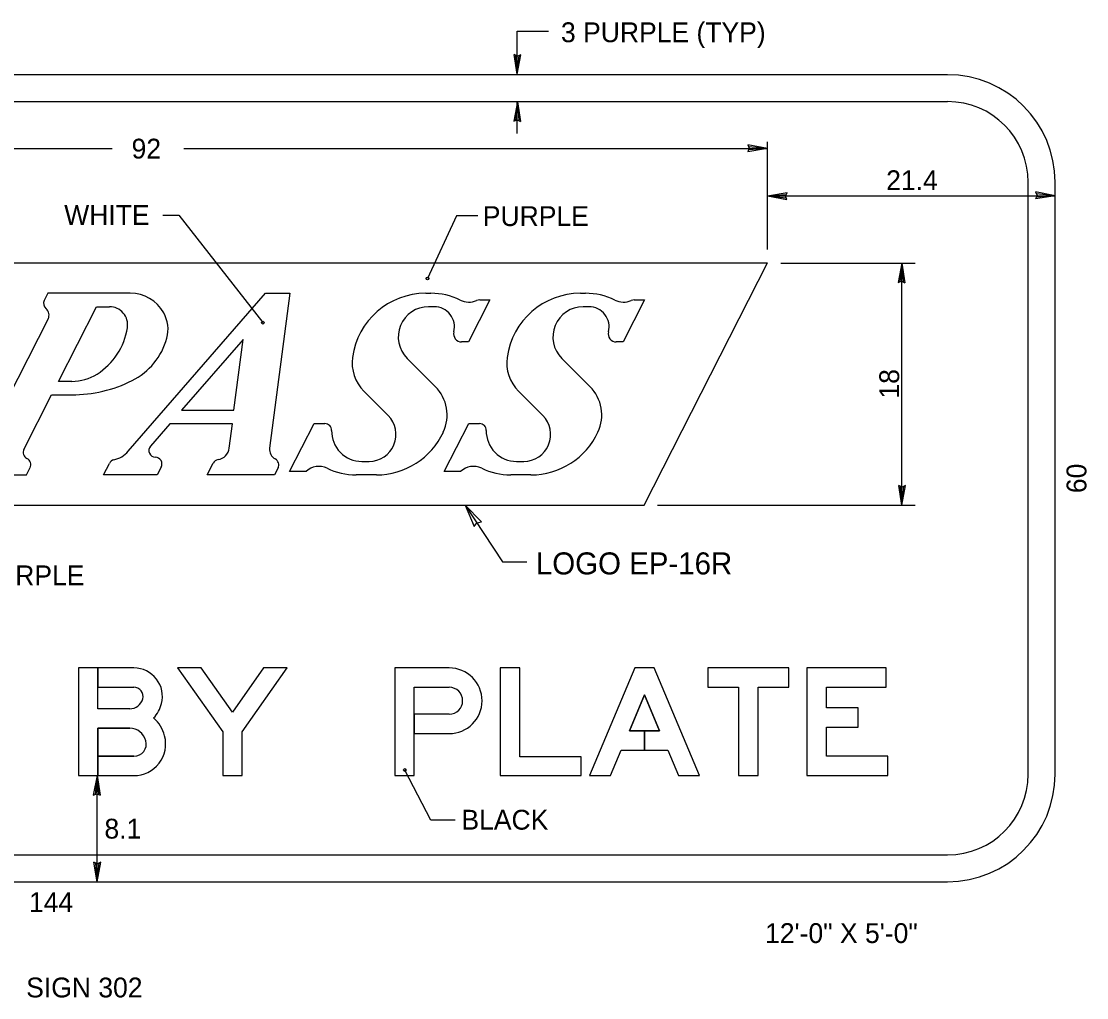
# Model space of a CAD drawing. Extents: x 319706 to 320449, y 1621775 to 1622117.
# Drawn here: x 319941.2 to 320016.4, y 1622047.8 to 1622116.7 of the extents above; entities that cross this region are included whole.
import ezdxf

# ---------------------------------------------------------------- set-up
doc = ezdxf.new("R2010")
doc.units = 0
for name, color, linetype in [('1', 7, 'Continuous'), ('52', 7, 'Continuous'), ('GSBWFill', 7, 'Continuous'), ('SignPanel', 7, 'Continuous')]:
    doc.layers.add(name, color=color, linetype=linetype)

msp = doc.modelspace()

# ---------------------------------------------------------------- linework, layer by layer
at = {"layer": '1'}
for p, q in [((319976.192, 1622116.021), (319978.396, 1622116.007)), ((319976.192, 1622112.926), (319976.192, 1622116.021)), ((319976.192, 1622108.782), (319976.192, 1622111.041)), ((319993.862, 1622100.591), (319993.862, 1622108.191)), ((319906.462, 1622107.716), (319947.578, 1622107.716)), ((319952.634, 1622107.716), (319993.862, 1622107.716)), ((319993.862, 1622104.391), (320014.192, 1622104.391)), ((319951.159, 1622103.026), (319952.29, 1622103.026)), ((319952.29, 1622103.026), (319958.216, 1622095.427)), ((319971.899, 1622102.972), (319969.851, 1622098.552)), ((319973.407, 1622102.972), (319971.899, 1622102.972)), ((319994.812, 1622099.639), (320004.312, 1622099.639)), ((320003.362, 1622082.539), (320003.362, 1622099.639)), ((319972.523, 1622082.541), (319975.141, 1622078.543)), ((319986.099, 1622082.539), (320004.312, 1622082.539)), ((319975.141, 1622078.543), (319976.861, 1622078.543)), ((319970.079, 1622060.29), (319968.252, 1622063.833)), ((319946.507, 1622055.939), (319946.507, 1622063.439)), ((319971.815, 1622060.29), (319970.079, 1622060.29))]:
    msp.add_line(p, q, dxfattribs=at)
for centre in [(319969.851, 1622098.552), (319958.216, 1622095.426), (319968.252, 1622063.833)]:
    msp.add_circle(centre, 0.095, dxfattribs=at)
at = {"layer": '52'}
for p, q in [((319976.185, 1622112.964), (319975.965, 1622114.353)), ((319976.207, 1622114.243), (319975.965, 1622114.353)), ((319976.185, 1622112.964), (319976.092, 1622114.294)), ((319976.185, 1622112.964), (319976.453, 1622114.345)), ((319976.185, 1622112.964), (319976.324, 1622114.291)), ((319976.453, 1622114.345), (319976.207, 1622114.243)), ((319976.211, 1622111.028), (319975.943, 1622109.648)), ((319976.211, 1622111.028), (319976.072, 1622109.701)), ((319976.211, 1622111.028), (319976.431, 1622109.639)), ((319976.211, 1622111.028), (319976.304, 1622109.698)), ((319975.943, 1622109.648), (319976.189, 1622109.749)), ((319976.189, 1622109.749), (319976.431, 1622109.639)), ((319993.862, 1622107.716), (319992.481, 1622107.984)), ((319992.481, 1622107.984), (319992.583, 1622107.738)), ((319992.583, 1622107.738), (319992.473, 1622107.496)), ((319993.862, 1622107.716), (319992.473, 1622107.496)), ((319993.862, 1622107.716), (319992.532, 1622107.623)), ((319993.862, 1622107.716), (319992.534, 1622107.855)), ((319993.862, 1622104.391), (319995.251, 1622104.612)), ((319993.862, 1622104.391), (319995.192, 1622104.484)), ((319993.862, 1622104.391), (319995.242, 1622104.123)), ((319993.862, 1622104.391), (319995.189, 1622104.253)), ((319995.14, 1622104.37), (319995.251, 1622104.612)), ((319995.242, 1622104.123), (319995.14, 1622104.37)), ((320012.913, 1622104.413), (320012.803, 1622104.171)), ((320014.192, 1622104.391), (320012.803, 1622104.171)), ((320014.192, 1622104.391), (320012.811, 1622104.659)), ((320012.811, 1622104.659), (320012.913, 1622104.413)), ((320014.192, 1622104.391), (320012.862, 1622104.298)), ((320014.192, 1622104.391), (320012.864, 1622104.53)), ((320003.362, 1622099.639), (320003.094, 1622098.259)), ((320003.362, 1622099.639), (320003.223, 1622098.312)), ((320003.362, 1622099.639), (320003.582, 1622098.25)), ((320003.362, 1622099.639), (320003.455, 1622098.309)), ((320003.094, 1622098.259), (320003.34, 1622098.361)), ((320003.34, 1622098.361), (320003.582, 1622098.25)), ((320003.362, 1622082.539), (320003.141, 1622083.928)), ((320003.383, 1622083.818), (320003.141, 1622083.928)), ((320003.362, 1622082.539), (320003.269, 1622083.869)), ((320003.362, 1622082.539), (320003.63, 1622083.92)), ((320003.362, 1622082.539), (320003.5, 1622083.867)), ((320003.63, 1622083.92), (320003.383, 1622083.818)), ((319972.523, 1622082.541), (319973.146, 1622081.022)), ((319973.657, 1622081.357), (319972.523, 1622082.541)), ((319973.146, 1622081.022), (319973.339, 1622081.295)), ((319973.339, 1622081.295), (319973.657, 1622081.357)), ((319946.507, 1622063.439), (319946.239, 1622062.059)), ((319946.507, 1622063.439), (319946.368, 1622062.112)), ((319946.507, 1622063.439), (319946.727, 1622062.05)), ((319946.507, 1622063.439), (319946.6, 1622062.109)), ((319946.239, 1622062.059), (319946.485, 1622062.16)), ((319946.485, 1622062.16), (319946.727, 1622062.05)), ((319946.507, 1622055.939), (319946.287, 1622057.328)), ((319946.529, 1622057.218), (319946.287, 1622057.328)), ((319946.507, 1622055.939), (319946.414, 1622057.269)), ((319946.507, 1622055.939), (319946.775, 1622057.32)), ((319946.507, 1622055.939), (319946.646, 1622057.267)), ((319946.775, 1622057.32), (319946.529, 1622057.218))]:
    msp.add_line(p, q, dxfattribs=at)
at = {"layer": 'GSBWFill'}
for p, q in [((319968.912, 1622069.672), (319971.383, 1622069.672)), ((319968.912, 1622069.672), (319971.383, 1622069.672)), ((319968.912, 1622069.672), (319971.383, 1622069.672)), ((319968.912, 1622066.403), (319971.383, 1622066.403)), ((319945.195, 1622063.439), (319949.11, 1622063.439))]:
    msp.add_line(p, q, dxfattribs=at)
for points in [[(319949.11, 1622071.041), (319945.195, 1622071.041), (319945.195, 1622063.439)], [(319948.815, 1622068.152), (319946.563, 1622068.152), (319946.563, 1622071.041), (319945.195, 1622071.041), (319945.195, 1622063.439), (319946.563, 1622063.439)], [(319948.815, 1622068.152), (319946.563, 1622068.152), (319946.563, 1622071.041), (319945.195, 1622071.041), (319945.195, 1622063.439), (319946.563, 1622063.439)], [(319949.11, 1622071.041), (319946.563, 1622071.041), (319946.563, 1622069.672), (319949.11, 1622069.672)], [(319949.11, 1622071.041), (319946.563, 1622071.041), (319946.563, 1622069.672), (319949.11, 1622069.672)], [(319971.383, 1622071.041), (319967.544, 1622071.041), (319967.544, 1622063.439), (319968.912, 1622063.439), (319968.912, 1622066.403)], [(319971.383, 1622071.041), (319967.544, 1622071.041), (319967.544, 1622063.439), (319968.912, 1622063.439), (319968.912, 1622069.672)], [(319971.383, 1622071.041), (319967.544, 1622071.041), (319967.544, 1622063.439), (319968.912, 1622063.439), (319968.912, 1622069.672)], [(319948.815, 1622068.152), (319946.563, 1622068.152), (319946.563, 1622069.672), (319949.11, 1622069.672)], [(319971.383, 1622067.772), (319968.912, 1622067.772), (319968.912, 1622069.672)], [(319971.383, 1622067.772), (319968.913, 1622067.772), (319968.913, 1622066.403), (319971.383, 1622066.403)], [(319971.383, 1622067.772), (319968.913, 1622067.772), (319968.913, 1622066.403), (319971.383, 1622066.403)], [(319948.815, 1622066.784), (319946.563, 1622066.784), (319946.563, 1622064.807), (319949.11, 1622064.807)], [(319946.563, 1622063.439), (319946.563, 1622066.784), (319948.815, 1622066.784)], [(319946.563, 1622063.439), (319946.563, 1622066.784), (319948.815, 1622066.784)], [(319949.11, 1622064.807), (319946.563, 1622064.807), (319946.563, 1622063.439), (319949.11, 1622063.439)], [(319949.11, 1622064.807), (319946.563, 1622064.807), (319946.563, 1622063.439), (319949.11, 1622063.439)]]:
    msp.add_lwpolyline(points, dxfattribs=at)
for points in [[(319956.749, 1622066.518), (319959.942, 1622071.041), (319958.267, 1622071.041), (319956.065, 1622067.921), (319953.863, 1622071.041), (319952.188, 1622071.041), (319955.381, 1622066.518), (319955.381, 1622063.439), (319956.749, 1622063.439)], [(319956.749, 1622066.518), (319959.942, 1622071.041), (319958.267, 1622071.041), (319956.065, 1622067.921), (319953.863, 1622071.041), (319952.188, 1622071.041), (319955.381, 1622066.518), (319955.381, 1622063.439), (319956.749, 1622063.439)], [(319956.749, 1622066.518), (319959.942, 1622071.041), (319958.267, 1622071.041), (319956.065, 1622067.921), (319953.863, 1622071.041), (319952.188, 1622071.041), (319955.381, 1622066.518), (319955.381, 1622063.439), (319956.749, 1622063.439)], [(319980.695, 1622063.439), (319980.695, 1622064.769), (319976.362, 1622064.769), (319976.362, 1622071.041), (319974.994, 1622071.041), (319974.994, 1622063.439)], [(319980.695, 1622063.439), (319980.695, 1622064.769), (319976.362, 1622064.769), (319976.362, 1622071.041), (319974.994, 1622071.041), (319974.994, 1622063.439)], [(319980.695, 1622063.439), (319980.695, 1622064.769), (319976.362, 1622064.769), (319976.362, 1622071.041), (319974.994, 1622071.041), (319974.994, 1622063.439)], [(319983.537, 1622065.225), (319986.822, 1622065.225), (319987.573, 1622063.439), (319989.057, 1622063.439), (319985.864, 1622071.041), (319984.496, 1622071.041), (319981.303, 1622063.439), (319982.787, 1622063.439)], [(319986.248, 1622066.594), (319985.18, 1622066.594), (319985.18, 1622065.225), (319986.822, 1622065.225), (319987.573, 1622063.439), (319989.057, 1622063.439), (319985.864, 1622071.041), (319984.496, 1622071.041), (319981.303, 1622063.439), (319982.787, 1622063.439), (319983.537, 1622065.225), (319985.18, 1622065.225), (319985.18, 1622066.594), (319984.112, 1622066.594), (319985.18, 1622069.136)], [(319986.248, 1622066.594), (319985.18, 1622066.594), (319985.18, 1622065.225), (319986.822, 1622065.225), (319987.573, 1622063.439), (319989.057, 1622063.439), (319985.864, 1622071.041), (319984.496, 1622071.041), (319981.303, 1622063.439), (319982.787, 1622063.439), (319983.537, 1622065.225), (319985.18, 1622065.225), (319985.18, 1622066.594), (319984.112, 1622066.594), (319985.18, 1622069.136)], [(319989.665, 1622069.672), (319991.831, 1622069.672), (319991.831, 1622063.439), (319993.2, 1622063.439), (319993.2, 1622069.672), (319995.366, 1622069.672), (319995.366, 1622071.041), (319989.665, 1622071.041)], [(319989.665, 1622069.672), (319991.831, 1622069.672), (319991.831, 1622063.439), (319993.2, 1622063.439), (319993.2, 1622069.672), (319995.366, 1622069.672), (319995.366, 1622071.041), (319989.665, 1622071.041)], [(319989.665, 1622069.672), (319991.831, 1622069.672), (319991.831, 1622063.439), (319993.2, 1622063.439), (319993.2, 1622069.672), (319995.366, 1622069.672), (319995.366, 1622071.041), (319989.665, 1622071.041)], [(320002.36, 1622064.807), (319998.027, 1622064.807), (319998.027, 1622066.852), (320000.269, 1622066.852), (320000.269, 1622068.22), (319998.027, 1622068.22), (319998.027, 1622069.672), (320002.246, 1622069.672), (320002.246, 1622071.041), (319996.659, 1622071.041), (319996.659, 1622063.439), (320002.36, 1622063.439)], [(320002.36, 1622064.807), (319998.027, 1622064.807), (319998.027, 1622066.852), (320000.269, 1622066.852), (320000.269, 1622068.22), (319998.027, 1622068.22), (319998.027, 1622069.672), (320002.246, 1622069.672), (320002.246, 1622071.041), (319996.659, 1622071.041), (319996.659, 1622063.439), (320002.36, 1622063.439)], [(320002.36, 1622064.807), (319998.027, 1622064.807), (319998.027, 1622066.852), (320000.269, 1622066.852), (320000.269, 1622068.22), (319998.027, 1622068.22), (319998.027, 1622069.672), (320002.246, 1622069.672), (320002.246, 1622071.041), (319996.659, 1622071.041), (319996.659, 1622063.439), (320002.36, 1622063.439)], [(319986.248, 1622066.594), (319985.18, 1622069.136), (319984.112, 1622066.594)]]:
    msp.add_lwpolyline(points, close=True, dxfattribs=at)
for centre, radius, start, end in [((319949.11, 1622069.026), 2.014, 345.52249, 90), ((319949.11, 1622069.026), 2.014, 345.52249, 90), ((319949.11, 1622069.026), 2.014, 345.52249, 90), ((319949.11, 1622069.026), 0.646, 345.52249, 90), ((319949.11, 1622069.026), 0.646, 345.52249, 90), ((319949.11, 1622069.026), 0.646, 345.52249, 90), ((319948.815, 1622069.102), 0.95, 270, 345.52249), ((319948.815, 1622069.102), 0.95, 270, 345.52249), ((319948.815, 1622069.102), 0.95, 270, 345.52249), ((319948.815, 1622069.102), 2.319, 316.7114, 345.52249), ((319948.815, 1622069.102), 2.319, 316.7114, 345.52249), ((319948.815, 1622069.102), 2.319, 316.7114, 345.52249), ((319948.815, 1622065.605), 2.547, 14.47751, 48.4921), ((319948.815, 1622065.605), 2.547, 14.47751, 48.4921), ((319948.815, 1622065.605), 2.547, 14.47751, 48.4921), ((319948.815, 1622065.605), 1.178, 14.47751, 90), ((319948.815, 1622065.605), 1.178, 14.47751, 90), ((319948.815, 1622065.605), 1.178, 14.47751, 90), ((319949.11, 1622065.681), 2.243, 270, 14.47751), ((319949.11, 1622065.681), 2.243, 270, 14.47751), ((319949.11, 1622065.681), 2.243, 270, 14.47751), ((319949.11, 1622065.681), 0.874, 270, 14.47751), ((319949.11, 1622065.681), 0.874, 270, 14.47751), ((319949.11, 1622065.681), 0.874, 270, 14.47751)]:
    msp.add_arc(centre, radius, start, end, dxfattribs=at)
for major_axis in [(0, 2.319), (0, 2.319), (0, 2.319), (0, 0.95), (0, 0.95), (0, 0.95)]:
    msp.add_ellipse((319971.383, 1622068.722), major_axis=major_axis, ratio=0.999994, start_param=3.141593, end_param=6.283185, dxfattribs=at)
at = {"layer": 'SignPanel'}
for p, q in [((319884.992, 1622112.941), (320006.593, 1622112.941)), ((319884.992, 1622111.041), (320006.593, 1622111.041)), ((320012.293, 1622063.541), (320012.293, 1622105.341)), ((320014.193, 1622063.541), (320014.193, 1622105.341)), ((319939.669, 1622099.641), (319993.863, 1622099.641)), ((319985.149, 1622082.541), (319993.863, 1622099.641)), ((319943.037, 1622097.503), (319942.778, 1622096.996)), ((319948.855, 1622097.503), (319943.037, 1622097.503)), ((319948.709, 1622086.346), (319958.41, 1622097.503)), ((319958.41, 1622097.503), (319960.12, 1622097.503)), ((319960.12, 1622097.503), (319958.698, 1622086.571)), ((319969.729, 1622097.503), (319970.089, 1622097.503)), ((319980.655, 1622097.503), (319981.015, 1622097.503)), ((319974.248, 1622097.027), (319972.738, 1622094.065)), ((319973.536, 1622097.027), (319974.248, 1622097.027)), ((319985.174, 1622097.027), (319983.664, 1622094.065)), ((319984.46, 1622097.027), (319985.174, 1622097.027)), ((319943.782, 1622091.281), (319946.47, 1622096.553)), ((319946.47, 1622096.553), (319947.386, 1622096.553)), ((319970.33, 1622096.553), (319969.924, 1622096.553)), ((319981.256, 1622096.553), (319980.848, 1622096.553)), ((319943.053, 1622095.707), (319938.349, 1622086.476)), ((319956.819, 1622094.226), (319952.482, 1622089.237)), ((319956.17, 1622089.237), (319956.819, 1622094.226)), ((319972.738, 1622094.065), (319972.264, 1622094.065)), ((319983.664, 1622094.065), (319983.188, 1622094.065)), ((319968.411, 1622092.904), (319970.402, 1622090.913)), ((319979.337, 1622092.904), (319981.328, 1622090.913)), ((319944.723, 1622091.281), (319943.782, 1622091.281)), ((319967.069, 1622088.872), (319965.36, 1622090.581)), ((319977.995, 1622088.872), (319976.286, 1622090.581)), ((319941.333, 1622086.476), (319943.298, 1622090.331)), ((319943.298, 1622090.331), (319944.723, 1622090.331)), ((319952.482, 1622089.237), (319956.17, 1622089.237)), ((319951.659, 1622088.287), (319950.281, 1622086.705)), ((319956.073, 1622088.287), (319951.659, 1622088.287)), ((319955.848, 1622086.571), (319956.073, 1622088.287)), ((319960.113, 1622084.916), (319961.838, 1622088.302)), ((319961.838, 1622088.302), (319962.601, 1622088.302)), ((319971.038, 1622084.916), (319972.764, 1622088.302)), ((319972.764, 1622088.302), (319973.527, 1622088.302)), ((319946.961, 1622084.677), (319947.375, 1622085.491)), ((319954.292, 1622084.677), (319954.712, 1622085.503)), ((319965.212, 1622085.627), (319965.726, 1622085.627)), ((319976.138, 1622085.627), (319976.65, 1622085.627)), ((319936.768, 1622084.677), (319941.518, 1622084.677)), ((319941.518, 1622084.677), (319941.776, 1622085.186)), ((319950.761, 1622084.677), (319946.961, 1622084.677)), ((319951.041, 1622085.226), (319950.761, 1622084.677)), ((319959.042, 1622084.677), (319954.292, 1622084.677)), ((319959.292, 1622085.167), (319959.042, 1622084.677)), ((319961.268, 1622084.916), (319960.113, 1622084.916)), ((319966.237, 1622084.677), (319964.808, 1622084.677)), ((319972.192, 1622084.916), (319971.038, 1622084.916)), ((319977.161, 1622084.677), (319975.732, 1622084.677)), ((319938.409, 1622082.541), (319985.149, 1622082.541)), ((319884.992, 1622057.841), (320006.593, 1622057.841)), ((319884.992, 1622055.941), (320006.593, 1622055.941))]:
    msp.add_line(p, q, dxfattribs=at)
for centre, radius, start, end in [((320006.592, 1622105.339), 7.6, 0, 90), ((320006.592, 1622105.339), 5.7, 0, 90), ((319948.855, 1622094.794), 2.708, 29.43149, 90), ((319969.729, 1622092.277), 5.225, 90, 172.30892), ((319970.089, 1622092.752), 4.75, 64.08957, 90), ((319980.654, 1622092.277), 5.225, 90, 172.30892), ((319981.014, 1622092.752), 4.75, 64.08957, 90), ((319943.2, 1622096.779), 0.475, 152.97842, 231.16017), ((319972.787, 1622098.306), 1.425, 244.08957, 292.03474), ((319973.536, 1622096.457), 0.57, 90, 112.03474), ((319983.712, 1622098.306), 1.425, 244.08957, 292.03474), ((319984.461, 1622096.457), 0.57, 90, 112.03474), ((319942.545, 1622095.965), 0.57, 333.00266, 51.16017), ((319947.385, 1622095.269), 1.283, 351.07601, 90), ((319949.144, 1622094.957), 2.375, 344.70738, 29.43149), ((319969.923, 1622094.414), 2.138, 90, 225), ((319970.33, 1622095.127), 1.425, 345.69149, 90), ((319980.848, 1622094.414), 2.138, 90, 225), ((319981.256, 1622095.127), 1.425, 345.69149, 90), ((319943.959, 1622095.807), 4.75, 302.42062, 351.07601), ((319946.853, 1622095.584), 4.75, 296.64315, 344.70738), ((319972.264, 1622094.634), 0.57, 165.69149, 270), ((319983.189, 1622094.634), 0.57, 165.69149, 270), ((319967.375, 1622092.595), 2.85, 172.30892, 225), ((319978.3, 1622092.595), 2.85, 172.30892, 225), ((319944.723, 1622094.604), 3.325, 270, 302.42062), ((319944.723, 1622099.829), 9.5, 270, 296.64315), ((319968.387, 1622088.896), 2.85, 334.94996, 45), ((319979.313, 1622088.896), 2.85, 334.94996, 45), ((319962.601, 1622087.825), 0.475, 358.66645, 90), ((319965.725, 1622087.527), 1.9, 270, 45), ((319973.526, 1622087.825), 0.475, 358.66645, 90), ((319976.65, 1622087.527), 1.9, 270, 45), ((319965.213, 1622087.764), 2.138, 178.66645, 270), ((319966.236, 1622089.902), 5.225, 270, 334.94996), ((319976.138, 1622087.764), 2.138, 178.66645, 270), ((319977.161, 1622089.902), 5.225, 270, 334.94996), ((319941.757, 1622086.259), 0.475, 152.98839, 244.78323), ((319947.275, 1622087.591), 1.9, 282.71621, 318.99659), ((319950.64, 1622086.391), 0.475, 138.98241, 268.68694), ((319954.906, 1622086.692), 0.95, 279.2397, 352.56317), ((319959.451, 1622086.471), 0.76, 172.58839, 241.86732), ((319941.352, 1622085.4), 0.475, 333.02391, 64.78322), ((319947.798, 1622085.274), 0.475, 102.71621, 153.02391), ((319950.618, 1622085.442), 0.475, 332.97842, 88.68694), ((319955.135, 1622085.286), 0.475, 99.2397, 153.02391), ((319958.869, 1622085.382), 0.475, 332.97842, 61.86732), ((319962.178, 1622083.945), 1.33, 64.37946, 133.18921), ((319964.807, 1622089.427), 4.75, 244.37946, 270), ((319973.103, 1622083.945), 1.33, 64.37946, 133.18921), ((319975.732, 1622089.427), 4.75, 244.37946, 270), ((320006.592, 1622063.539), 7.6, 270, 360), ((320006.592, 1622063.539), 5.7, 270, 0)]:
    msp.add_arc(centre, radius, start, end, dxfattribs=at)

# ---------------------------------------------------------------- texts
at = {"layer": '1'}
for s, height, p in [('3 PURPLE (TYP)', 1.4, (319979.28, 1622115.233)), ('92', 1.4, (319948.946, 1622107.016)), ('21.4', 1.4, (320002.254, 1622104.783)), ('WHITE', 1.4, (319944.186, 1622102.327)), ('PURPLE', 1.4, (319973.758, 1622102.251)), ('LOGO EP-16R', 1.55556, (319977.507, 1622077.646)), ('PURPLE', 1.4, (319938.122, 1622076.879)), ('BLACK', 1.4, (319972.248, 1622059.621)), ('8.1', 1.4, (319947.028, 1622058.989)), ('144', 1.4, (319941.7, 1622053.802)), ('12\'-0" X 5\'-0"', 1.4, (319993.699, 1622051.613)), ('SIGN 302', 1.4, (319941.498, 1622047.773))]:
    msp.add_text(s, height=height, dxfattribs=at).set_placement(p)
for s, p in [('18', (320003.171, 1622090.064)), ('60', (320016.399, 1622083.385))]:
    msp.add_text(s, height=1.4, rotation=90, dxfattribs=at).set_placement(p)

doc.saveas('drawing.dxf')
